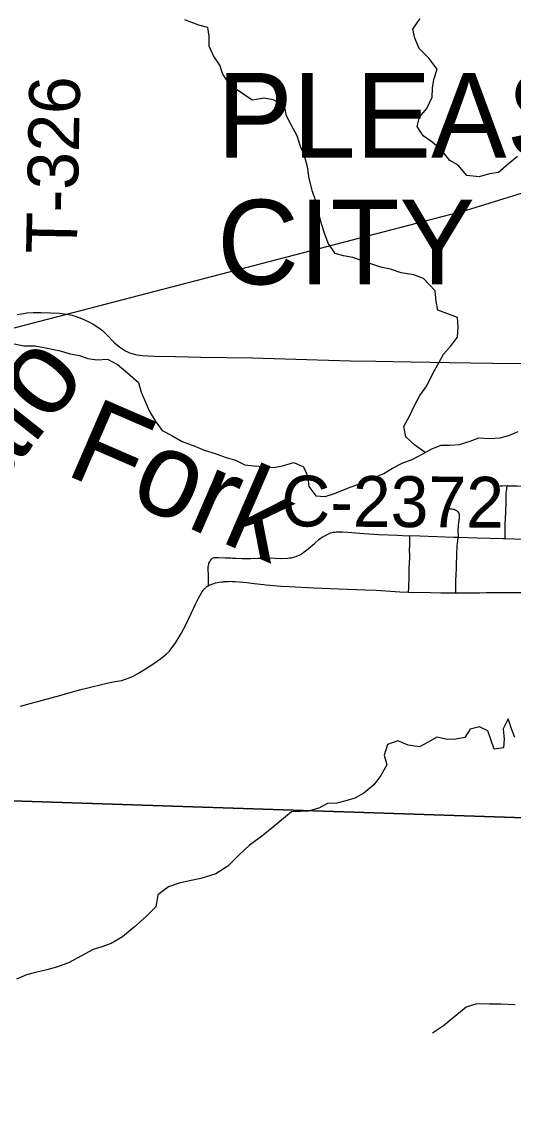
# Model space of a CAD drawing. Extents: x 0 to 34, y 0 to 22.
# Drawn here: x 27.656 to 28.206, y 18.296 to 19.507 of the extents above; entities that cross this region are included whole.
import ezdxf

# ---------------------------------------------------------------- set-up
doc = ezdxf.new("R2010")
doc.units = 0
for name, color, linetype in [('GM_X_Corporation', 7, 'Continuous'), ('GM_X_Corporation_Text', 7, 'Continuous'), ('GM_X_County_Road_Text', 7, 'Continuous'), ('GM_X_Minor_River', 7, 'Continuous'), ('GM_X_Minor_River_Text', 7, 'Continuous'), ('GM_X_Rail_Line', 7, 'Continuous'), ('GM_X_State_Route', 7, 'Continuous'), ('GM_X_Township_Road', 7, 'Continuous'), ('GM_X_Township_Road_Text', 7, 'Continuous')]:
    doc.layers.add(name, color=color, linetype=linetype)

msp = doc.modelspace()

# ---------------------------------------------------------------- linework, layer by layer
at = {"layer": 'GM_X_Corporation'}
for points in [[(26.6535, 14.621), (27.01, 14.6164), (27.046, 14.6155), (27.043, 14.755), (27.052, 15.403), (27.0676, 16.5549), (27.0694, 16.6556), (27.0775, 16.888), (27.0944, 18.0731), (27.1039, 18.5696), (27.1064, 18.6537), (27.3971, 18.6436), (28.3421, 18.6121), (28.7772, 18.6028), (29.0074, 18.5935), (29.6561, 18.5791), (29.6772, 18.5786), (30.101, 18.5701), (30.3167, 18.565), (30.3167, 20.9), (23.5167, 20.9)], [(26.3378, 16.673), (27.0694, 16.6556), (27.0775, 16.888), (27.0944, 18.0731), (27.1039, 18.5696), (27.1064, 18.6537), (27.3971, 18.6436), (28.3421, 18.6121), (28.7772, 18.6028), (29.0074, 18.5935), (29.6561, 18.5791), (29.6772, 18.5786), (30.101, 18.5701), (30.3167, 18.565), (30.3167, 20.9), (25.1014, 20.9)], [(23.5167, 14.1), (30.3167, 14.1), (30.3167, 18.565), (30.101, 18.5701), (29.6772, 18.5786), (29.6561, 18.5791), (29.0074, 18.5935), (28.7772, 18.6028), (28.3421, 18.6121), (27.3971, 18.6436), (27.1064, 18.6537), (27.1039, 18.5696), (27.0944, 18.0731), (27.0775, 16.888), (27.0694, 16.6556), (27.0676, 16.5549), (27.052, 15.403), (27.043, 14.755), (27.046, 14.6155), (27.01, 14.6164), (26.6535, 14.621)], [(30.3167, 14.5373), (30.3167, 18.565), (30.101, 18.5701), (29.6772, 18.5786), (29.6561, 18.5791), (29.0074, 18.5935), (28.7772, 18.6028), (28.3421, 18.6121), (27.3971, 18.6436), (27.1064, 18.6537), (27.1039, 18.5696), (27.0944, 18.0731)]]:
    msp.add_lwpolyline(points, dxfattribs=at)
at = {"layer": 'GM_X_Minor_River'}
for points in [[(28.2105, 19.356), (28.2004, 19.3479), (28.1891, 19.3383), (28.1789, 19.3367), (28.1676, 19.3332), (28.1536, 19.3349), (28.144, 19.3462), (28.1345, 19.3514), (28.1258, 19.3627), (28.1143, 19.3724), (28.1048, 19.3791), (28.0979, 19.3896), (28.1005, 19.3999), (28.1087, 19.4098), (28.115, 19.4224), (28.1153, 19.4323), (28.1167, 19.4421), (28.1204, 19.4539), (28.1112, 19.4659), (28.1002, 19.4768), (28.0955, 19.4885), (28.0932, 19.4983), (28.1014, 19.5105)], [(28.107, 19.0248), (28.095, 19.0335), (28.0855, 19.0424), (28.0831, 19.0542), (28.0898, 19.0664), (28.095, 19.0774), (28.1009, 19.0888), (28.1088, 19.0995), (28.1158, 19.114), (28.1222, 19.1251), (28.1274, 19.135), (28.136, 19.1445), (28.1431, 19.1541), (28.1441, 19.1654), (28.1433, 19.176), (28.1311, 19.1805), (28.1213, 19.1841), (28.1193, 19.194), (28.1181, 19.2057), (28.1051, 19.2196), (28.0945, 19.2236), (28.0801, 19.2261), (28.0683, 19.2302), (28.0573, 19.2323), (28.0475, 19.2357), (28.038, 19.239), (28.0262, 19.243), (28.0157, 19.2448), (28.0062, 19.2477), (27.9985, 19.259), (27.9946, 19.2692), (27.9911, 19.2809), (27.9872, 19.2953), (27.9845, 19.3062), (27.981, 19.3168), (27.9771, 19.3315), (27.9755, 19.3444), (27.972, 19.3569), (27.9677, 19.3674), (27.9638, 19.3791), (27.9569, 19.3916), (27.9519, 19.4014), (27.9495, 19.4127), (27.937, 19.4194), (27.9268, 19.4212), (27.9136, 19.4191), (27.9041, 19.4255), (27.8892, 19.4355), (27.8808, 19.448), (27.8773, 19.4582), (27.8701, 19.4687), (27.8654, 19.4796), (27.8653, 19.4906), (27.8637, 19.5004), (27.8539, 19.503), (27.8383, 19.5089)], [(27.6453, 19.1469), (27.6578, 19.1444), (27.6707, 19.1441), (27.6858, 19.1413), (27.6972, 19.1391), (27.7097, 19.1355), (27.7203, 19.1333), (27.7297, 19.13), (27.74, 19.1286), (27.7517, 19.1295), (27.7627, 19.1235), (27.7741, 19.1142), (27.7863, 19.1033), (27.7894, 19.0923), (27.7941, 19.0814), (27.7983, 19.0716), (27.8056, 19.0592), (27.8129, 19.0494), (27.8235, 19.0438), (27.8353, 19.0371), (27.8493, 19.032), (27.8599, 19.0275), (27.872, 19.0239), (27.8842, 19.0195), (27.8948, 19.0162), (27.9054, 19.011), (27.9153, 19.01), (27.927, 19.0093), (27.9372, 19.0083), (27.9474, 19.0099), (27.9602, 19.0138), (27.9708, 19.009), (27.9755, 18.9988), (27.9767, 18.9871), (27.9847, 18.9766)], [(27.9847, 18.9766), (27.9953, 18.9756), (28.0055, 18.9791), (28.0213, 18.9853), (28.0383, 18.9916), (28.0496, 18.9966), (28.0609, 19.0013), (28.0706, 19.0074), (28.0812, 19.0129), (28.0925, 19.0171), (28.1045, 19.0233), (28.1143, 19.0291), (28.1249, 19.033), (28.1347, 19.0331), (28.1453, 19.034), (28.1573, 19.0375), (28.1671, 19.0414), (28.1792, 19.0408), (28.1909, 19.0413), (28.2007, 19.044), (28.2109, 19.0483)], [(28.2075, 18.7062), (28.2036, 18.716), (28.1997, 18.7269), (28.1941, 18.7159), (28.1954, 18.7045), (28.1947, 18.6947), (28.1841, 18.693), (28.1803, 18.704), (28.1772, 18.7138), (28.1677, 18.7182), (28.1575, 18.7155), (28.1515, 18.706), (28.1413, 18.7043), (28.1315, 18.7038), (28.1201, 18.7064), (28.1104, 18.701), (28.1006, 18.6959), (28.0881, 18.6977), (28.0763, 18.7025), (28.065, 18.6982), (28.061, 18.6864), (28.0641, 18.6755), (28.0574, 18.6637), (28.0495, 18.6533), (28.0383, 18.6441), (28.0285, 18.6383), (28.0183, 18.6352), (28.0081, 18.6328), (27.9979, 18.6323), (27.9881, 18.6273), (27.9761, 18.6238), (27.9674, 18.6234), (27.9575, 18.6231)], [(27.9575, 18.6231), (27.9378, 18.6067), (27.9238, 18.5954), (27.9105, 18.5859), (27.8988, 18.5749), (27.8863, 18.5624), (27.8727, 18.5537), (27.856, 18.5484), (27.8435, 18.5458), (27.8318, 18.5432), (27.8197, 18.539), (27.808, 18.5303), (27.8057, 18.5167), (27.795, 18.5061), (27.7818, 18.4943), (27.7685, 18.4833), (27.7557, 18.4758), (27.7454, 18.472), (27.7356, 18.469), (27.7224, 18.4618), (27.708, 18.4542), (27.6944, 18.4493), (27.6838, 18.4463), (27.6709, 18.4433), (27.6611, 18.4406), (27.6497, 18.4357)], [(28.2078, 18.407), (28.1915, 18.4078), (28.1791, 18.4078), (28.1647, 18.4082), (28.153, 18.4044), (28.1401, 18.3942), (28.1276, 18.3836), (28.1151, 18.3756)]]:
    msp.add_lwpolyline(points, dxfattribs=at)
at = {"layer": 'GM_X_Rail_Line'}
msp.add_lwpolyline([(28.8018, 19.5008), (28.2457, 19.3243), (28.1529, 19.2955), (27.3181, 19.0787), (26.8719, 18.963)], dxfattribs=at)
at = {"layer": 'GM_X_State_Route'}
msp.add_lwpolyline([(27.6507, 19.1793), (27.6577, 19.1806), (27.6615, 19.181), (27.6684, 19.1815), (27.6771, 19.1816), (27.6877, 19.1813), (27.6978, 19.1807), (27.7057, 19.1797), (27.7119, 19.1785), (27.7167, 19.1771), (27.7226, 19.175), (27.7301, 19.1716), (27.7356, 19.1686), (27.7409, 19.1652), (27.7459, 19.1614), (27.751, 19.1567), (27.7596, 19.1477), (27.7637, 19.1441), (27.7676, 19.1412), (27.7718, 19.1387), (27.7762, 19.1366), (27.779, 19.1356), (27.7843, 19.1342), (27.791, 19.1333), (27.7971, 19.1329), (27.8046, 19.1326), (27.8276, 19.1322), (27.8562, 19.1317), (27.9139, 19.1308), (27.95, 19.1297), (28.0233, 19.1276), (28.0518, 19.127), (28.091, 19.1263), (28.1338, 19.1256), (28.1823, 19.125), (28.2246, 19.1246)], dxfattribs=at)
at = {"layer": 'GM_X_Township_Road'}
for points in [[(28.1987, 18.9879), (28.1999, 18.9878), (28.2028, 18.9878), (28.2101, 18.9875), (28.2156, 18.9874), (28.2243, 18.9879), (28.2304, 18.9886), (28.2365, 18.9899), (28.2484, 18.9928), (28.2492, 18.9929)], [(28.1905, 18.9877), (28.1916, 18.9878), (28.1934, 18.9878), (28.1987, 18.9879)], [(28.1965, 18.9286), (28.1965, 18.9329), (28.1967, 18.9447), (28.1973, 18.9578), (28.1976, 18.9696), (28.1978, 18.9796), (28.1983, 18.9839), (28.1987, 18.9879)], [(28.1311, 18.9621), (28.1332, 18.9621), (28.1354, 18.962), (28.1366, 18.9619), (28.1379, 18.9617), (28.1393, 18.9614), (28.1404, 18.961), (28.1412, 18.9606), (28.142, 18.9601), (28.1427, 18.9595), (28.1434, 18.9588), (28.1441, 18.958), (28.1445, 18.9574), (28.1448, 18.9567), (28.145, 18.9561)], [(28.145, 18.9561), (28.1451, 18.9552), (28.1452, 18.9542), (28.1452, 18.9536), (28.1452, 18.9527), (28.1451, 18.9517), (28.1448, 18.9494), (28.1441, 18.9436), (28.1439, 18.9413), (28.1437, 18.9389), (28.1438, 18.9302)], [(27.8648, 18.9), (27.8651, 18.9012), (27.8659, 18.9027), (27.8667, 18.904), (27.8675, 18.9052), (27.8682, 18.906), (27.8689, 18.9066), (27.8697, 18.9071), (27.871, 18.9074), (27.8737, 18.9075), (27.8756, 18.9075), (27.8836, 18.9072), (27.886, 18.9071), (27.8891, 18.907), (27.8915, 18.9069), (27.8953, 18.9067), (27.9021, 18.9064), (27.9119, 18.9064), (27.9199, 18.9067), (27.923, 18.9069), (27.9285, 18.907), (27.9391, 18.9066), (27.9465, 18.9065), (27.9534, 18.9068), (27.9554, 18.907), (27.9571, 18.9072), (27.9589, 18.9076), (27.9607, 18.9081), (27.9625, 18.9087), (27.9642, 18.9094), (27.9659, 18.9102), (27.9675, 18.911), (27.9696, 18.9122), (27.9717, 18.9137), (27.9761, 18.9171), (27.9831, 18.9233), (27.9882, 18.9278), (27.9906, 18.9295)], [(27.9906, 18.9295), (27.993, 18.931), (27.9942, 18.9317), (27.9955, 18.9323), (27.9968, 18.933), (27.998, 18.9336), (27.9995, 18.9343), (28.0011, 18.935), (28.0026, 18.9354), (28.004, 18.9357), (28.006, 18.9359), (28.0075, 18.9361), (28.0098, 18.9362), (28.0115, 18.9362), (28.0145, 18.9362), (28.0206, 18.9359), (28.0385, 18.9344), (28.0552, 18.9332), (28.0658, 18.9328), (28.0757, 18.9324), (28.088, 18.9319), (28.09, 18.932)], [(28.0884, 18.8688), (28.0886, 18.8737), (28.0889, 18.8778), (28.0891, 18.8822), (28.0891, 18.8903), (28.0892, 18.8922), (28.0892, 18.8959), (28.0893, 18.9009), (28.0897, 18.9083), (28.0897, 18.9102), (28.0897, 18.912), (28.0896, 18.9139), (28.0896, 18.9164), (28.0897, 18.9204), (28.0898, 18.9227), (28.09, 18.932)], [(28.09, 18.932), (28.101, 18.9317), (28.1391, 18.9304), (28.1438, 18.9302)], [(28.1414, 18.8679), (28.1415, 18.8726), (28.1415, 18.8757), (28.1415, 18.8818), (28.1416, 18.888), (28.1419, 18.8954), (28.1425, 18.9139), (28.1427, 18.9174), (28.1429, 18.9208), (28.1431, 18.9233), (28.1434, 18.9262), (28.1438, 18.9302)], [(28.1438, 18.9302), (28.1651, 18.9295), (28.1943, 18.9287), (28.1965, 18.9286)], [(28.1965, 18.9286), (28.2061, 18.9284), (28.216, 18.9282), (28.2259, 18.928), (28.2396, 18.9279), (28.2439, 18.9282), (28.2483, 18.9289), (28.2495, 18.9291)], [(27.8645, 18.8759), (27.8645, 18.8819), (27.8646, 18.8843), (27.8645, 18.888), (27.8642, 18.8941), (27.8643, 18.8971), (27.8645, 18.8985), (27.8648, 18.9)], [(27.8645, 18.8759), (27.8657, 18.8765), (27.8683, 18.8777), (27.8711, 18.8786), (27.8725, 18.8791), (27.8746, 18.8795), (27.8766, 18.8799), (27.8792, 18.8803), (27.8809, 18.8804), (27.8817, 18.8806), (27.8853, 18.8808), (27.8871, 18.8808), (27.8885, 18.8809), (27.8911, 18.8808), (27.8943, 18.8806), (27.9073, 18.8794), (27.9158, 18.8785), (27.9264, 18.8774)], [(27.6543, 18.7413), (27.6693, 18.7453), (27.6789, 18.7478), (27.6981, 18.753), (27.7202, 18.7594), (27.7448, 18.7656), (27.7508, 18.767), (27.76, 18.7687), (27.7673, 18.7701), (27.7716, 18.7713), (27.7757, 18.7728), (27.7803, 18.7748), (27.7864, 18.7781), (27.797, 18.7847), (27.8058, 18.7905), (27.8128, 18.7958), (27.8172, 18.7994), (27.8208, 18.8029), (27.8237, 18.8063), (27.8273, 18.8114), (27.8297, 18.815), (27.8341, 18.8226), (27.8387, 18.8314), (27.8451, 18.8448), (27.85, 18.8554), (27.8534, 18.862), (27.8565, 18.8674), (27.8588, 18.8709), (27.8598, 18.8721), (27.8603, 18.8727), (27.8608, 18.8733), (27.8617, 18.8741), (27.8623, 18.8746), (27.8629, 18.875), (27.8635, 18.8754), (27.8645, 18.8759)], [(27.9264, 18.8774), (27.9293, 18.8771), (27.9455, 18.8756), (27.9548, 18.8752), (27.9821, 18.8737), (28.0106, 18.8725), (28.0398, 18.8714), (28.0522, 18.871), (28.0682, 18.8698), (28.0787, 18.8692), (28.0884, 18.8688)], [(28.0884, 18.8688), (28.1129, 18.8684), (28.1247, 18.8681), (28.139, 18.8679), (28.1414, 18.8679)], [(28.1414, 18.8679), (28.155, 18.8679), (28.1612, 18.8679), (28.1631, 18.8679), (28.168, 18.8681), (28.1752, 18.8685), (28.1777, 18.8685), (28.1801, 18.8684), (28.1819, 18.8684), (28.1844, 18.8684), (28.1862, 18.8684), (28.1955, 18.8684), (28.206, 18.8684), (28.2152, 18.8683), (28.2183, 18.8684), (28.2208, 18.8683), (28.2257, 18.8683), (28.2326, 18.8682), (28.2382, 18.8682), (28.2412, 18.8682), (28.2486, 18.868)]]:
    msp.add_lwpolyline(points, dxfattribs=at)

# ---------------------------------------------------------------- texts
at = {"layer": 'GM_X_Corporation_Text'}
for s, p in [('PLEASANT', (27.8743, 19.3547)), ('CITY', (27.8743, 19.213))]:
    msp.add_text(s, height=0.0947, rotation=0, dxfattribs=at).set_placement(p)
at = {"layer": 'GM_X_County_Road_Text'}
msp.add_text('C-2372', height=0.05682, rotation=359.6397, dxfattribs=at).set_placement((27.9458, 18.9424))
at = {"layer": 'GM_X_Minor_River_Text'}
for s, rotation, p in [('Buffalo', 51.577, (27.4847, 18.8013)), ('Fork', 336.5812, (27.7021, 19.0012))]:
    msp.add_text(s, height=0.09469, rotation=rotation, dxfattribs=at).set_placement(p)
at = {"layer": 'GM_X_Township_Road_Text'}
msp.add_text('T-326', height=0.05682, rotation=88.8743, dxfattribs=at).set_placement((27.7172, 19.2468))

doc.saveas('drawing.dxf')
